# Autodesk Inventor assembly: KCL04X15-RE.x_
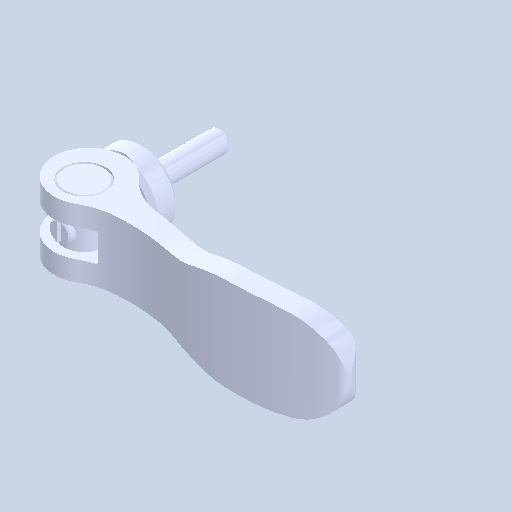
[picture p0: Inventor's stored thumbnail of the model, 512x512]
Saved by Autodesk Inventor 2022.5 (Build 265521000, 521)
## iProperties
Created: 2024-08
Part Number: KCL04X15-RE.x_
Document SubType Name: Assembly
Designer: ImaoCorp
Author: ImaoCorp
Sending System: SOLIDWORKS 2022-2022290
MC: AMD64
MC_MODEL: Intel64 Family 6 Model 60 Stepping 3, GenuineIntel
OS: Windows_NT
FRU: Parasolid Version 33.1, build 260,  4-25-2022
FORMAT: text
GUISE: transmit
KEY: FILEKCL04X15-RE.x_t
DATE: Thu Aug 29 10:47:46 2024
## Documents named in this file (5)
- Y:\5.更新分\2024年対応\1001_KCL\データ\kcl04x15-re\KCL04X15-RE.x_.iam
- Y:\5.更新分\2024年対応\1001_KCL\データ\kcl04x15-re\KCL4X15-RE_01.ipt
- Y:\5.更新分\2024年対応\1001_KCL\データ\kcl04x15-re\KCL4X15-RE_02.ipt
- Y:\5.更新分\2024年対応\1001_KCL\データ\kcl04x15-re\KCL4X15-RE_03.ipt
- Y:\5.更新分\2024年対応\1001_KCL\データ\kcl04x15-re\KCL4X15-RE_04.ipt
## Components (4 placed, 4 different names)
1. KCL4X15-RE_01
2. KCL4X15-RE_02
3. KCL4X15-RE_03
4. KCL4X15-RE_04
